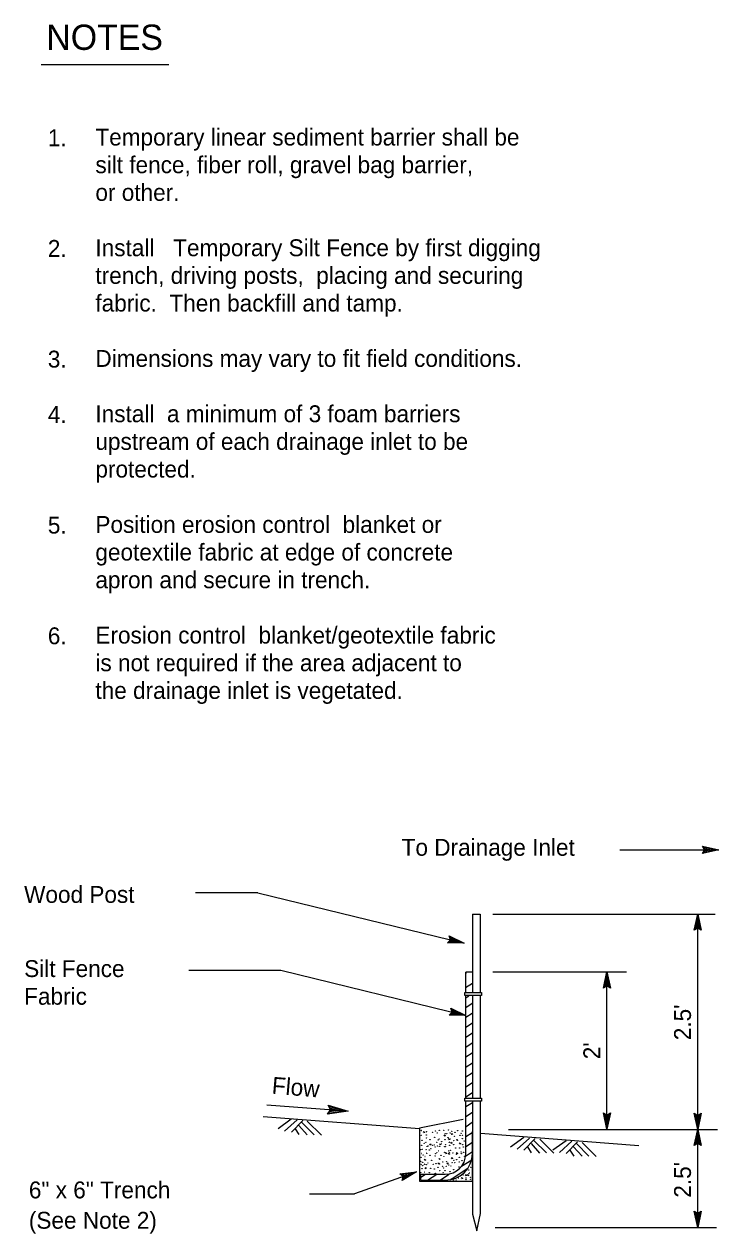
# Model space of a CAD drawing. Extents: x 6708945 to 6710368, y 1871409 to 1872338.
# Drawn here: x 6710120.7 to 6710367.6, y 1871745.5 to 1872175.7 of the extents above; entities that cross this region are included whole.
import ezdxf

# ---------------------------------------------------------------- set-up
doc = ezdxf.new("R2010")
doc.units = 0
for name, color, linetype in [('1 Control', 7, 'Continuous'), ('56 Stg 3 Anno', 7, 'Continuous'), ('57 Undefined', 7, 'Continuous'), ('59 Soundwall Ann', 7, 'Continuous'), ('60 Nongeo Data', 7, 'Continuous')]:
    doc.layers.add(name, color=color, linetype=linetype)

msp = doc.modelspace()

# ---------------------------------------------------------------- linework, layer by layer
at = {"layer": '1 Control'}
for p, q in [((6710361.8, 1871883.35), (6710361.8, 1871883.35)), ((6710361.8, 1871880.79), (6710361.8, 1871880.79)), ((6710367.56, 1871882.07), (6710367.56, 1871882.07)), ((6710271.77, 1871851.46), (6710271.77, 1871851.46)), ((6710271.16, 1871848.97), (6710271.16, 1871848.97)), ((6710277.06, 1871848.85), (6710277.06, 1871848.85)), ((6710228.77, 1871791.21), (6710228.77, 1871791.21)), ((6710228.52, 1871788.02), (6710228.52, 1871788.02)), ((6710235.82, 1871789.06), (6710235.82, 1871789.06))]:
    msp.add_line(p, q, dxfattribs=at)
for points in [[(6710361.8, 1871883.35), (6710367.56, 1871882.07), (6710361.8, 1871880.79), (6710362, 1871881.13), (6710366.22, 1871882.06), (6710362, 1871883.01), (6710362.21, 1871882.67), (6710364.91, 1871882.07), (6710362.21, 1871881.47), (6710362.41, 1871881.81), (6710363.58, 1871882.07), (6710362.41, 1871882.33), (6710362.57, 1871882.07), (6710361.8, 1871880.79), (6710362.57, 1871882.07)], [(6710271.77, 1871851.46), (6710277.06, 1871848.85), (6710271.16, 1871848.97), (6710271.44, 1871849.26), (6710275.76, 1871849.16), (6710271.89, 1871851.08), (6710272, 1871850.71), (6710274.48, 1871849.48), (6710271.72, 1871849.54), (6710272, 1871849.82), (6710273.2, 1871849.79), (6710272.12, 1871850.33), (6710272.21, 1871850.03), (6710271.16, 1871848.97), (6710272.21, 1871850.03)], [(6710228.77, 1871791.21), (6710235.82, 1871789.06), (6710228.52, 1871788.02), (6710228.81, 1871788.42), (6710234.16, 1871789.18), (6710228.99, 1871790.77), (6710229.21, 1871790.32), (6710232.52, 1871789.31), (6710229.1, 1871788.83), (6710229.39, 1871789.23), (6710230.87, 1871789.44), (6710229.43, 1871789.88), (6710229.6, 1871789.53), (6710228.52, 1871788.02), (6710229.6, 1871789.53)]]:
    msp.add_lwpolyline(points, close=True, dxfattribs=at)
at = {"layer": '56 Stg 3 Anno'}
for p, q in [((6710332.36, 1871882.07), (6710367.56, 1871882.07)), ((6710287.23, 1871859.19), (6710366.26, 1871859.19)), ((6710358.78, 1871853.43), (6710360.07, 1871859.19)), ((6710360.07, 1871782.62), (6710360.07, 1871859.19)), ((6710360.07, 1871859.19), (6710360.07, 1871859.19)), ((6710360.07, 1871859.19), (6710361.34, 1871853.43)), ((6710360.07, 1871854.19), (6710358.78, 1871853.43)), ((6710359.12, 1871853.63), (6710360.07, 1871857.86)), ((6710359.47, 1871853.86), (6710360.06, 1871856.53)), ((6710359.8, 1871854.03), (6710360.06, 1871855.21)), ((6710360.06, 1871856.53), (6710360.67, 1871853.82)), ((6710360.06, 1871855.21), (6710360.32, 1871854.05)), ((6710360.07, 1871857.85), (6710361, 1871853.65)), ((6710361.34, 1871853.43), (6710360.07, 1871854.19)), ((6710358.78, 1871853.43), (6710358.78, 1871853.43)), ((6710361.34, 1871853.43), (6710361.34, 1871853.43)), ((6710287.23, 1871838.66), (6710334.72, 1871838.66)), ((6710326.53, 1871832.9), (6710327.82, 1871838.66)), ((6710326.53, 1871832.9), (6710327.82, 1871838.66)), ((6710326.88, 1871833.11), (6710327.82, 1871837.33)), ((6710326.88, 1871833.11), (6710327.82, 1871837.33)), ((6710327.82, 1871782.74), (6710327.82, 1871838.66)), ((6710327.82, 1871838.66), (6710327.82, 1871838.66)), ((6710327.82, 1871838.66), (6710329.1, 1871832.9)), ((6710327.82, 1871838.66), (6710327.82, 1871838.66)), ((6710327.82, 1871838.66), (6710329.1, 1871832.9)), ((6710327.82, 1871837.32), (6710328.75, 1871833.12)), ((6710327.82, 1871837.32), (6710328.75, 1871833.12)), ((6710327.82, 1871833.67), (6710326.53, 1871832.9)), ((6710327.82, 1871833.67), (6710326.53, 1871832.9)), ((6710326.53, 1871832.9), (6710326.53, 1871832.9)), ((6710326.53, 1871832.9), (6710326.53, 1871832.9)), ((6710327.22, 1871833.33), (6710327.82, 1871836.01)), ((6710327.22, 1871833.33), (6710327.82, 1871836.01)), ((6710327.55, 1871833.5), (6710327.82, 1871834.68)), ((6710327.55, 1871833.5), (6710327.82, 1871834.68)), ((6710327.82, 1871836.01), (6710328.42, 1871833.3)), ((6710327.82, 1871836.01), (6710328.42, 1871833.3)), ((6710327.82, 1871834.68), (6710328.07, 1871833.52)), ((6710327.82, 1871834.68), (6710328.07, 1871833.52)), ((6710329.1, 1871832.9), (6710327.82, 1871833.67)), ((6710329.1, 1871832.9), (6710327.82, 1871833.67)), ((6710329.1, 1871832.9), (6710329.1, 1871832.9)), ((6710329.1, 1871832.9), (6710329.1, 1871832.9)), ((6710271.74, 1871823.29), (6710272.79, 1871824.35)), ((6710272.79, 1871824.35), (6710272.35, 1871825.78)), ((6710272.35, 1871825.78), (6710272.35, 1871825.78)), ((6710272.35, 1871825.78), (6710277.64, 1871823.16)), ((6710272.47, 1871825.4), (6710276.35, 1871823.48)), ((6710273.78, 1871824.11), (6710272.59, 1871824.14)), ((6710272.61, 1871825.01), (6710275.06, 1871823.79)), ((6710272.69, 1871824.65), (6710273.78, 1871824.11)), ((6710277.64, 1871823.16), (6710271.74, 1871823.29)), ((6710271.74, 1871823.29), (6710271.74, 1871823.29)), ((6710276.34, 1871823.48), (6710272.04, 1871823.57)), ((6710275.06, 1871823.79), (6710272.29, 1871823.85)), ((6710277.64, 1871823.16), (6710277.64, 1871823.16)), ((6710327.82, 1871782.74), (6710326.54, 1871788.5)), ((6710326.54, 1871788.5), (6710326.54, 1871788.5)), ((6710326.54, 1871788.5), (6710327.82, 1871787.73)), ((6710327.82, 1871784.07), (6710326.89, 1871788.27)), ((6710327.82, 1871785.39), (6710327.22, 1871788.1)), ((6710327.82, 1871786.71), (6710327.57, 1871787.88)), ((6710327.82, 1871787.73), (6710329.11, 1871788.5)), ((6710329.11, 1871788.5), (6710327.82, 1871782.74)), ((6710328.77, 1871788.29), (6710327.82, 1871784.06)), ((6710328.42, 1871788.06), (6710327.82, 1871785.39)), ((6710328.09, 1871787.89), (6710327.82, 1871786.71)), ((6710329.11, 1871788.5), (6710329.11, 1871788.5)), ((6710360.07, 1871782.62), (6710358.79, 1871788.38)), ((6710358.79, 1871788.38), (6710358.79, 1871788.38)), ((6710358.79, 1871788.38), (6710360.07, 1871787.61)), ((6710360.06, 1871783.95), (6710359.13, 1871788.15)), ((6710360.07, 1871785.27), (6710359.47, 1871787.98)), ((6710360.07, 1871786.6), (6710359.81, 1871787.76)), ((6710360.07, 1871787.61), (6710361.35, 1871788.38)), ((6710361.35, 1871788.38), (6710360.07, 1871782.62)), ((6710361.01, 1871788.17), (6710360.07, 1871783.94)), ((6710360.67, 1871787.95), (6710360.07, 1871785.27)), ((6710360.33, 1871787.78), (6710360.07, 1871786.6)), ((6710361.35, 1871788.38), (6710361.35, 1871788.38)), ((6710292.82, 1871782.62), (6710367.14, 1871782.62)), ((6710327.82, 1871782.74), (6710327.82, 1871782.74)), ((6710358.78, 1871776.86), (6710360.07, 1871782.62)), ((6710359.12, 1871777.07), (6710360.07, 1871781.29)), ((6710360.07, 1871747.79), (6710360.07, 1871782.62)), ((6710360.07, 1871782.62), (6710360.07, 1871782.62)), ((6710360.07, 1871782.62), (6710360.07, 1871782.62)), ((6710360.07, 1871782.62), (6710361.34, 1871776.86)), ((6710360.07, 1871781.28), (6710361, 1871777.08)), ((6710360.07, 1871777.63), (6710358.78, 1871776.86)), ((6710358.78, 1871776.86), (6710358.78, 1871776.86)), ((6710359.47, 1871777.29), (6710360.06, 1871779.97)), ((6710359.8, 1871777.46), (6710360.06, 1871778.64)), ((6710360.06, 1871779.97), (6710360.67, 1871777.25)), ((6710360.06, 1871778.64), (6710360.32, 1871777.48)), ((6710361.34, 1871776.86), (6710360.07, 1871777.63)), ((6710361.34, 1871776.86), (6710361.34, 1871776.86)), ((6710260.09, 1871767.51), (6710238.07, 1871759.75)), ((6710360.07, 1871747.79), (6710358.79, 1871753.55)), ((6710358.79, 1871753.55), (6710358.79, 1871753.55)), ((6710358.79, 1871753.55), (6710360.07, 1871752.78)), ((6710360.06, 1871749.13), (6710359.13, 1871753.33)), ((6710360.07, 1871750.44), (6710359.47, 1871753.16)), ((6710360.07, 1871751.77), (6710359.81, 1871752.93)), ((6710360.07, 1871752.78), (6710361.35, 1871753.55)), ((6710361.35, 1871753.55), (6710360.07, 1871747.79)), ((6710361.01, 1871753.34), (6710360.07, 1871749.12)), ((6710360.67, 1871753.12), (6710360.07, 1871750.44)), ((6710360.33, 1871752.95), (6710360.07, 1871751.77)), ((6710361.35, 1871753.55), (6710361.35, 1871753.55)), ((6710288.11, 1871747.79), (6710366.7, 1871747.79)), ((6710360.07, 1871747.79), (6710360.07, 1871747.79))]:
    msp.add_line(p, q, dxfattribs=at)
for points in [[(6710203.78, 1871866.76), (6710181.62, 1871866.76)], [(6710203.78, 1871866.76), (6710277.06, 1871848.85)], [(6710179.15, 1871839.22), (6710211.96, 1871839.22)], [(6710211.96, 1871839.22), (6710277.64, 1871823.16)], [(6710222.12, 1871759.75), (6710238.07, 1871759.75)]]:
    msp.add_lwpolyline(points, dxfattribs=at)
at = {"layer": '57 Undefined'}
for p, q in [((6710126.73, 1872161.3), (6710172.08, 1872161.3)), ((6710268.64, 1871764.64), (6710271.77, 1871766.67))]:
    msp.add_line(p, q, dxfattribs=at)
at = {"layer": '59 Soundwall Ann'}
for p, q in [((6710277.59, 1871833.05), (6710280.03, 1871834.63)), ((6710277.63, 1871829.43), (6710278.75, 1871830.16)), ((6710277.64, 1871826.02), (6710279.86, 1871827.46)), ((6710277.64, 1871822.49), (6710279.93, 1871823.97)), ((6710277.64, 1871818.96), (6710280.02, 1871820.5)), ((6710277.68, 1871815.45), (6710279.97, 1871816.93)), ((6710277.68, 1871811.92), (6710279.91, 1871813.36)), ((6710277.71, 1871808.4), (6710279.95, 1871809.85)), ((6710277.67, 1871801.31), (6710279.95, 1871802.79)), ((6710277.73, 1871804.88), (6710280, 1871806.35)), ((6710277.66, 1871797.77), (6710280, 1871799.29)), ((6710277.69, 1871794.26), (6710279.99, 1871795.75)), ((6710277.67, 1871790.71), (6710279.98, 1871792.21)), ((6710215.6, 1871786.2), (6710210.93, 1871782.8)), ((6710217.66, 1871785.98), (6710213.25, 1871782.02)), ((6710219.67, 1871785.78), (6710215.69, 1871781.62)), ((6710221.32, 1871785.6), (6710226.32, 1871780.61)), ((6710277.71, 1871787.21), (6710280.01, 1871788.7)), ((6710216.94, 1871782.8), (6710218.31, 1871780.75)), ((6710218.25, 1871783.98), (6710221.27, 1871780.64)), ((6710219.25, 1871785.14), (6710223.72, 1871780.67)), ((6710277.65, 1871780.11), (6710279.9, 1871781.56)), ((6710277.72, 1871783.68), (6710279.96, 1871785.14)), ((6710277.64, 1871776.57), (6710279.97, 1871778.07)), ((6710298.21, 1871779.77), (6710293.54, 1871776.36)), ((6710300.27, 1871779.54), (6710295.86, 1871775.59)), ((6710302.28, 1871779.35), (6710298.3, 1871775.18)), ((6710300.86, 1871777.55), (6710303.88, 1871774.21)), ((6710301.86, 1871778.71), (6710306.33, 1871774.24)), ((6710303.93, 1871779.17), (6710308.93, 1871774.18)), ((6710313.28, 1871778.61), (6710308.61, 1871775.2)), ((6710315.34, 1871778.38), (6710310.93, 1871774.43)), ((6710317.35, 1871778.19), (6710313.37, 1871774.02)), ((6710316.94, 1871777.55), (6710321.4, 1871773.08)), ((6710319, 1871778.01), (6710324, 1871773.02)), ((6710280.06, 1871774.6), (6710277.56, 1871772.98)), ((6710299.55, 1871776.37), (6710300.92, 1871774.31)), ((6710314.63, 1871775.21), (6710316, 1871773.15)), ((6710315.93, 1871776.39), (6710318.95, 1871773.05)), ((6710272.03, 1871764.71), (6710278.41, 1871768.84)), ((6710276.13, 1871769.49), (6710279.76, 1871771.84)), ((6710261.69, 1871765.64), (6710263.32, 1871766.7)), ((6710264.04, 1871764.57), (6710267.33, 1871766.7))]:
    msp.add_line(p, q, dxfattribs=at)
for points in [[(6710262.55, 1871781.5), (6710262.82, 1871781.83), (6710262.93, 1871781.5), (6710262.6, 1871781.39)], [(6710272.5, 1871780.87), (6710272.77, 1871781.2), (6710272.88, 1871780.87), (6710272.55, 1871780.76)], [(6710264.77, 1871777.19), (6710265.05, 1871777.52), (6710265.16, 1871777.19), (6710264.83, 1871777.08)], [(6710268.31, 1871777.21), (6710268.58, 1871777.54), (6710268.69, 1871777.21), (6710268.36, 1871777.1)], [(6710269.88, 1871780.34), (6710270.15, 1871780.67), (6710270.26, 1871780.34), (6710269.93, 1871780.23)], [(6710271.45, 1871779.04), (6710271.72, 1871779.37), (6710271.83, 1871779.04), (6710271.5, 1871778.93)], [(6710272.23, 1871777.73), (6710272.51, 1871778.06), (6710272.62, 1871777.73), (6710272.29, 1871777.62)], [(6710275.38, 1871777.47), (6710275.65, 1871777.8), (6710275.76, 1871777.47), (6710275.43, 1871777.36)], [(6710270.4, 1871774.07), (6710270.67, 1871774.4), (6710270.78, 1871774.07), (6710270.46, 1871773.96)], [(6710271.45, 1871773.81), (6710271.72, 1871774.14), (6710271.83, 1871773.81), (6710271.5, 1871773.7)], [(6710272.5, 1871772.24), (6710272.77, 1871772.57), (6710272.88, 1871772.24), (6710272.55, 1871772.13)], [(6710274.33, 1871774.07), (6710274.6, 1871774.4), (6710274.71, 1871774.07), (6710274.38, 1871773.96)], [(6710262.96, 1871771.71), (6710263.24, 1871772.04), (6710263.35, 1871771.71), (6710263.02, 1871771.6)], [(6710263.1, 1871768.74), (6710263.38, 1871769.07), (6710263.49, 1871768.74), (6710263.16, 1871768.63)], [(6710267.78, 1871770.41), (6710268.06, 1871770.74), (6710268.17, 1871770.41), (6710267.84, 1871770.3)], [(6710268.04, 1871771.98), (6710268.32, 1871772.31), (6710268.43, 1871771.98), (6710268.1, 1871771.87)], [(6710270.92, 1871770.41), (6710271.2, 1871770.74), (6710271.31, 1871770.41), (6710270.98, 1871770.3)], [(6710276.09, 1871765.13), (6710276.37, 1871765.46), (6710276.48, 1871765.13), (6710276.15, 1871765.02)], [(6710277.47, 1871766.23), (6710277.74, 1871766.56), (6710277.85, 1871766.23), (6710277.52, 1871766.12)], [(6710278.26, 1871766.23), (6710278.53, 1871766.56), (6710278.64, 1871766.23), (6710278.31, 1871766.12)]]:
    msp.add_lwpolyline(points, dxfattribs=at)
for centre in [(6710261.79, 1871782.22), (6710263.69, 1871781.76), (6710265.78, 1871781.53), (6710266.92, 1871782.1), (6710267.49, 1871781.3), (6710268.22, 1871782.32), (6710269.8, 1871782.24), (6710270.27, 1871781.15), (6710270.86, 1871781.15), (6710271.51, 1871782.38), (6710272.03, 1871781.3), (6710272.62, 1871781.88), (6710273.79, 1871781.59), (6710274.72, 1871782.19), (6710275.98, 1871781.25), (6710276.42, 1871782.03), (6710261.79, 1871780.51), (6710261.93, 1871776.98), (6710262.06, 1871778.7), (6710262.88, 1871777.62), (6710263.46, 1871778.06), (6710263.64, 1871780.6), (6710263.69, 1871779.53), (6710264.23, 1871776.75), (6710264.89, 1871778.93), (6710265.84, 1871776.9), (6710266.42, 1871777.04), (6710266.61, 1871779.83), (6710267.3, 1871778.07), (6710267.59, 1871776.75), (6710267.79, 1871778.81), (6710268.12, 1871779.26), (6710268.96, 1871777.49), (6710269.1, 1871778.22), (6710270.27, 1871778.95), (6710270.42, 1871777.2), (6710271.3, 1871779.68), (6710271.74, 1871778.07), (6710271.93, 1871776.94), (6710272.03, 1871779.25), (6710273.35, 1871778.57), (6710273.35, 1871777.2), (6710273.64, 1871780.12), (6710274.5, 1871779), (6710274.61, 1871778.73), (6710275.6, 1871780.53), (6710276.42, 1871779.33), (6710276.51, 1871780.47), (6710276.53, 1871777.2), (6710277.08, 1871778.52), (6710261.59, 1871775.43), (6710261.74, 1871772.71), (6710261.88, 1871774.05), (6710262.18, 1871775.58), (6710262.48, 1871773.54), (6710263.09, 1871772.98), (6710263.55, 1871775.45), (6710263.79, 1871776.46), (6710263.78, 1871774.15), (6710264.67, 1871775.29), (6710264.89, 1871773.36), (6710265.25, 1871775.72), (6710266.7, 1871773.12), (6710266.72, 1871776.31), (6710266.91, 1871773.97), (6710267.35, 1871774.41), (6710267.93, 1871775), (6710268.37, 1871776.61), (6710268.84, 1871773.36), (6710269.84, 1871773.09), (6710270.13, 1871776.46), (6710270.13, 1871774.41), (6710270.42, 1871776.46), (6710271.45, 1871775), (6710271.88, 1871774.41), (6710272.18, 1871775.14), (6710273.07, 1871774.18), (6710274.06, 1871776.04), (6710274.33, 1871773.8), (6710275.38, 1871772.7), (6710275.49, 1871776.04), (6710275.49, 1871776.04), (6710275.98, 1871774.56), (6710276.09, 1871773.96), (6710276.73, 1871776.35), (6710276.85, 1871774.46), (6710277.24, 1871773.08), (6710261.6, 1871771.27), (6710261.74, 1871770.15), (6710262.11, 1871768.67), (6710262.3, 1871770.94), (6710262.34, 1871769.69), (6710262.34, 1871769.69), (6710262.95, 1871770.25), (6710263.6, 1871770.11), (6710264.15, 1871770.71), (6710265.13, 1871768.76), (6710265.54, 1871771.59), (6710266.05, 1871770.2), (6710266.44, 1871768.51), (6710267.06, 1871770.44), (6710267.79, 1871769.14), (6710268.28, 1871770.32), (6710269.35, 1871769.49), (6710269.46, 1871771.01), (6710269.69, 1871768.85), (6710270.71, 1871769.43), (6710270.77, 1871771.16), (6710271.58, 1871770), (6710272.32, 1871769.58), (6710272.78, 1871770.76), (6710273.35, 1871768.29), (6710273.4, 1871771.61), (6710273.73, 1871770.78), (6710274.39, 1871771.88), (6710275.24, 1871769.27), (6710275.3, 1871771.02), (6710276.31, 1871771.5), (6710278.63, 1871768.2), (6710279.38, 1871769.08), (6710261.65, 1871767.23), (6710262.99, 1871767.41), (6710264.71, 1871767.27), (6710266.83, 1871767.01), (6710268.37, 1871767.89), (6710269.59, 1871767.22), (6710270.27, 1871767.97), (6710272.05, 1871767.61), (6710273.25, 1871764.63), (6710274.22, 1871764.67), (6710275.06, 1871765.28), (6710276.66, 1871766.36), (6710277.7, 1871764.77), (6710277.72, 1871765.35), (6710278.74, 1871766.91), (6710278.88, 1871767.17), (6710278.93, 1871764.17), (6710279.32, 1871764.86), (6710279.34, 1871765.62), (6710280.03, 1871767.51)]:
    msp.add_ellipse(centre, major_axis=(0.0548, 0), ratio=0.999983, dxfattribs=at)
at = {"layer": '60 Nongeo Data'}
for p, q in [((6710280.06, 1871859.19), (6710282.76, 1871859.19)), ((6710277.64, 1871831.33), (6710277.64, 1871838.53)), ((6710277.64, 1871793.74), (6710277.64, 1871830.21)), ((6710235.33, 1871789.06), (6710206.89, 1871791.23)), ((6710277.64, 1871773.78), (6710277.64, 1871792.63)), ((6710261.14, 1871782.8), (6710205.58, 1871787.05)), ((6710339.18, 1871776.83), (6710282.88, 1871781.14)), ((6710254.23, 1871766.81), (6710254.23, 1871766.81)), ((6710255.08, 1871764.4), (6710255.08, 1871764.4)), ((6710260.09, 1871767.51), (6710260.09, 1871767.51)), ((6710261.69, 1871764.57), (6710261.69, 1871766.7)), ((6710261.69, 1871766.7), (6710270.27, 1871766.7)), ((6710261.69, 1871764.57), (6710270.27, 1871764.57)), ((6710280.06, 1871752.45), (6710281.56, 1871746.59)), ((6710281.56, 1871746.57), (6710282.88, 1871752.72))]:
    msp.add_line(p, q, dxfattribs=at)
for points in [[(6710280.06, 1871859.19), (6710280.06, 1871831.32)], [(6710282.88, 1871831.31), (6710282.88, 1871859.19)], [(6710280.05, 1871838.53), (6710277.64, 1871838.53), (6710277.64, 1871838.11)], [(6710280.06, 1871830.17), (6710280.06, 1871793.74)], [(6710282.88, 1871793.74), (6710282.88, 1871830.2)], [(6710280.06, 1871792.63), (6710280.06, 1871752.45)], [(6710282.88, 1871752.72), (6710282.88, 1871792.63)], [(6710276.75, 1871786.1), (6710261.14, 1871783.09), (6710261.14, 1871764.18), (6710280.06, 1871764.18), (6710280.06, 1871781.9)]]:
    msp.add_lwpolyline(points, dxfattribs=at)
for points in [[(6710277.28, 1871831.29), (6710283.21, 1871831.29), (6710283.21, 1871830.18), (6710277.28, 1871830.18)], [(6710277.29, 1871793.74), (6710283.22, 1871793.74), (6710283.22, 1871792.63), (6710277.29, 1871792.63)], [(6710254.23, 1871766.81), (6710260.09, 1871767.51), (6710255.08, 1871764.4), (6710255.16, 1871764.78), (6710258.83, 1871767.07), (6710254.54, 1871766.56), (6710254.84, 1871766.31), (6710257.59, 1871766.63), (6710255.24, 1871765.17), (6710255.32, 1871765.56), (6710256.34, 1871766.2), (6710255.15, 1871766.05), (6710255.38, 1871765.86), (6710255.08, 1871764.4), (6710255.38, 1871765.86)]]:
    msp.add_lwpolyline(points, close=True, dxfattribs=at)
for centre, major_axis in [((6710270.39, 1871774.25), (-9.68, 0)), ((6710270.39, 1871773.9), (-7.23, 0))]:
    msp.add_ellipse(centre, major_axis=major_axis, ratio=0.999983, start_param=1.559282, end_param=3.125268, dxfattribs=at)
msp.add_ellipse((6710272.45, 1871764.94), major_axis=(0.0548, 0), ratio=0.999983, dxfattribs=at)

# ---------------------------------------------------------------- texts
at = {"layer": '57 Undefined'}
for s, height, p in [('NOTES', 9, (6710128.55, 1872166.53)), ('1.', 6, (6710129.09, 1872132.28)), ('Temporary linear sediment barrier shall be ', 6, (6710146, 1872132.52)), ('silt fence, fiber roll, gravel bag barrier, ', 6, (6710146, 1872122.68)), ('or other.', 6, (6710146, 1872112.84)), ('Install   Temporary Silt Fence by first digging ', 6, (6710146, 1872093.16)), ('2.', 6, (6710129.09, 1872092.92)), ('trench, driving posts,  placing and securing ', 6, (6710146, 1872083.32)), ('fabric.  Then backfill and tamp.', 6, (6710146, 1872073.48)), ('3.', 6, (6710129.09, 1872053.56)), ('Dimensions may vary to fit field conditions.', 6, (6710146, 1872053.8)), ('4.', 6, (6710129.09, 1872033.88)), ('Install  a minimum of 3 foam barriers ', 6, (6710146, 1872034.12)), ('upstream of each drainage inlet to be ', 6, (6710146, 1872024.28)), ('protected.', 6, (6710146, 1872014.44)), ('5.', 6, (6710129.09, 1871994.52)), ('Position erosion control  blanket or ', 6, (6710146, 1871994.76)), ('geotextile fabric at edge of concrete ', 6, (6710146, 1871984.92)), ('apron and secure in trench.', 6, (6710146, 1871975.08)), ('Erosion control  blanket/geotextile fabric ', 6, (6710146, 1871955.4)), ('6.', 6, (6710129.09, 1871955.16)), ('is not required if the area adjacent to ', 6, (6710146, 1871945.56)), ('the drainage inlet is vegetated.', 6, (6710146, 1871935.72)), ('To Drainage Inlet', 6, (6710254.84, 1871879.93)), ('Wood Post', 6, (6710120.66, 1871863.18)), ('Silt Fence', 6, (6710120.69, 1871836.8)), ('Fabric', 6, (6710120.69, 1871826.96)), ('6" x 6" Trench ', 6, (6710122.35, 1871758.09)), ('(See Note 2)', 6, (6710122.35, 1871747.29))]:
    msp.add_text(s, height=height, dxfattribs=at).set_placement(p)
for s, rotation, p in [("2.5'", 90, (6710357.67, 1871814.34)), ("2'", 90, (6710325.42, 1871807.57)), ('Flow', 355.2879, (6710208.54, 1871795.35)), ("2.5'", 90, (6710357.67, 1871758.34))]:
    msp.add_text(s, height=6, rotation=rotation, dxfattribs=at).set_placement(p)

doc.saveas('drawing.dxf')
